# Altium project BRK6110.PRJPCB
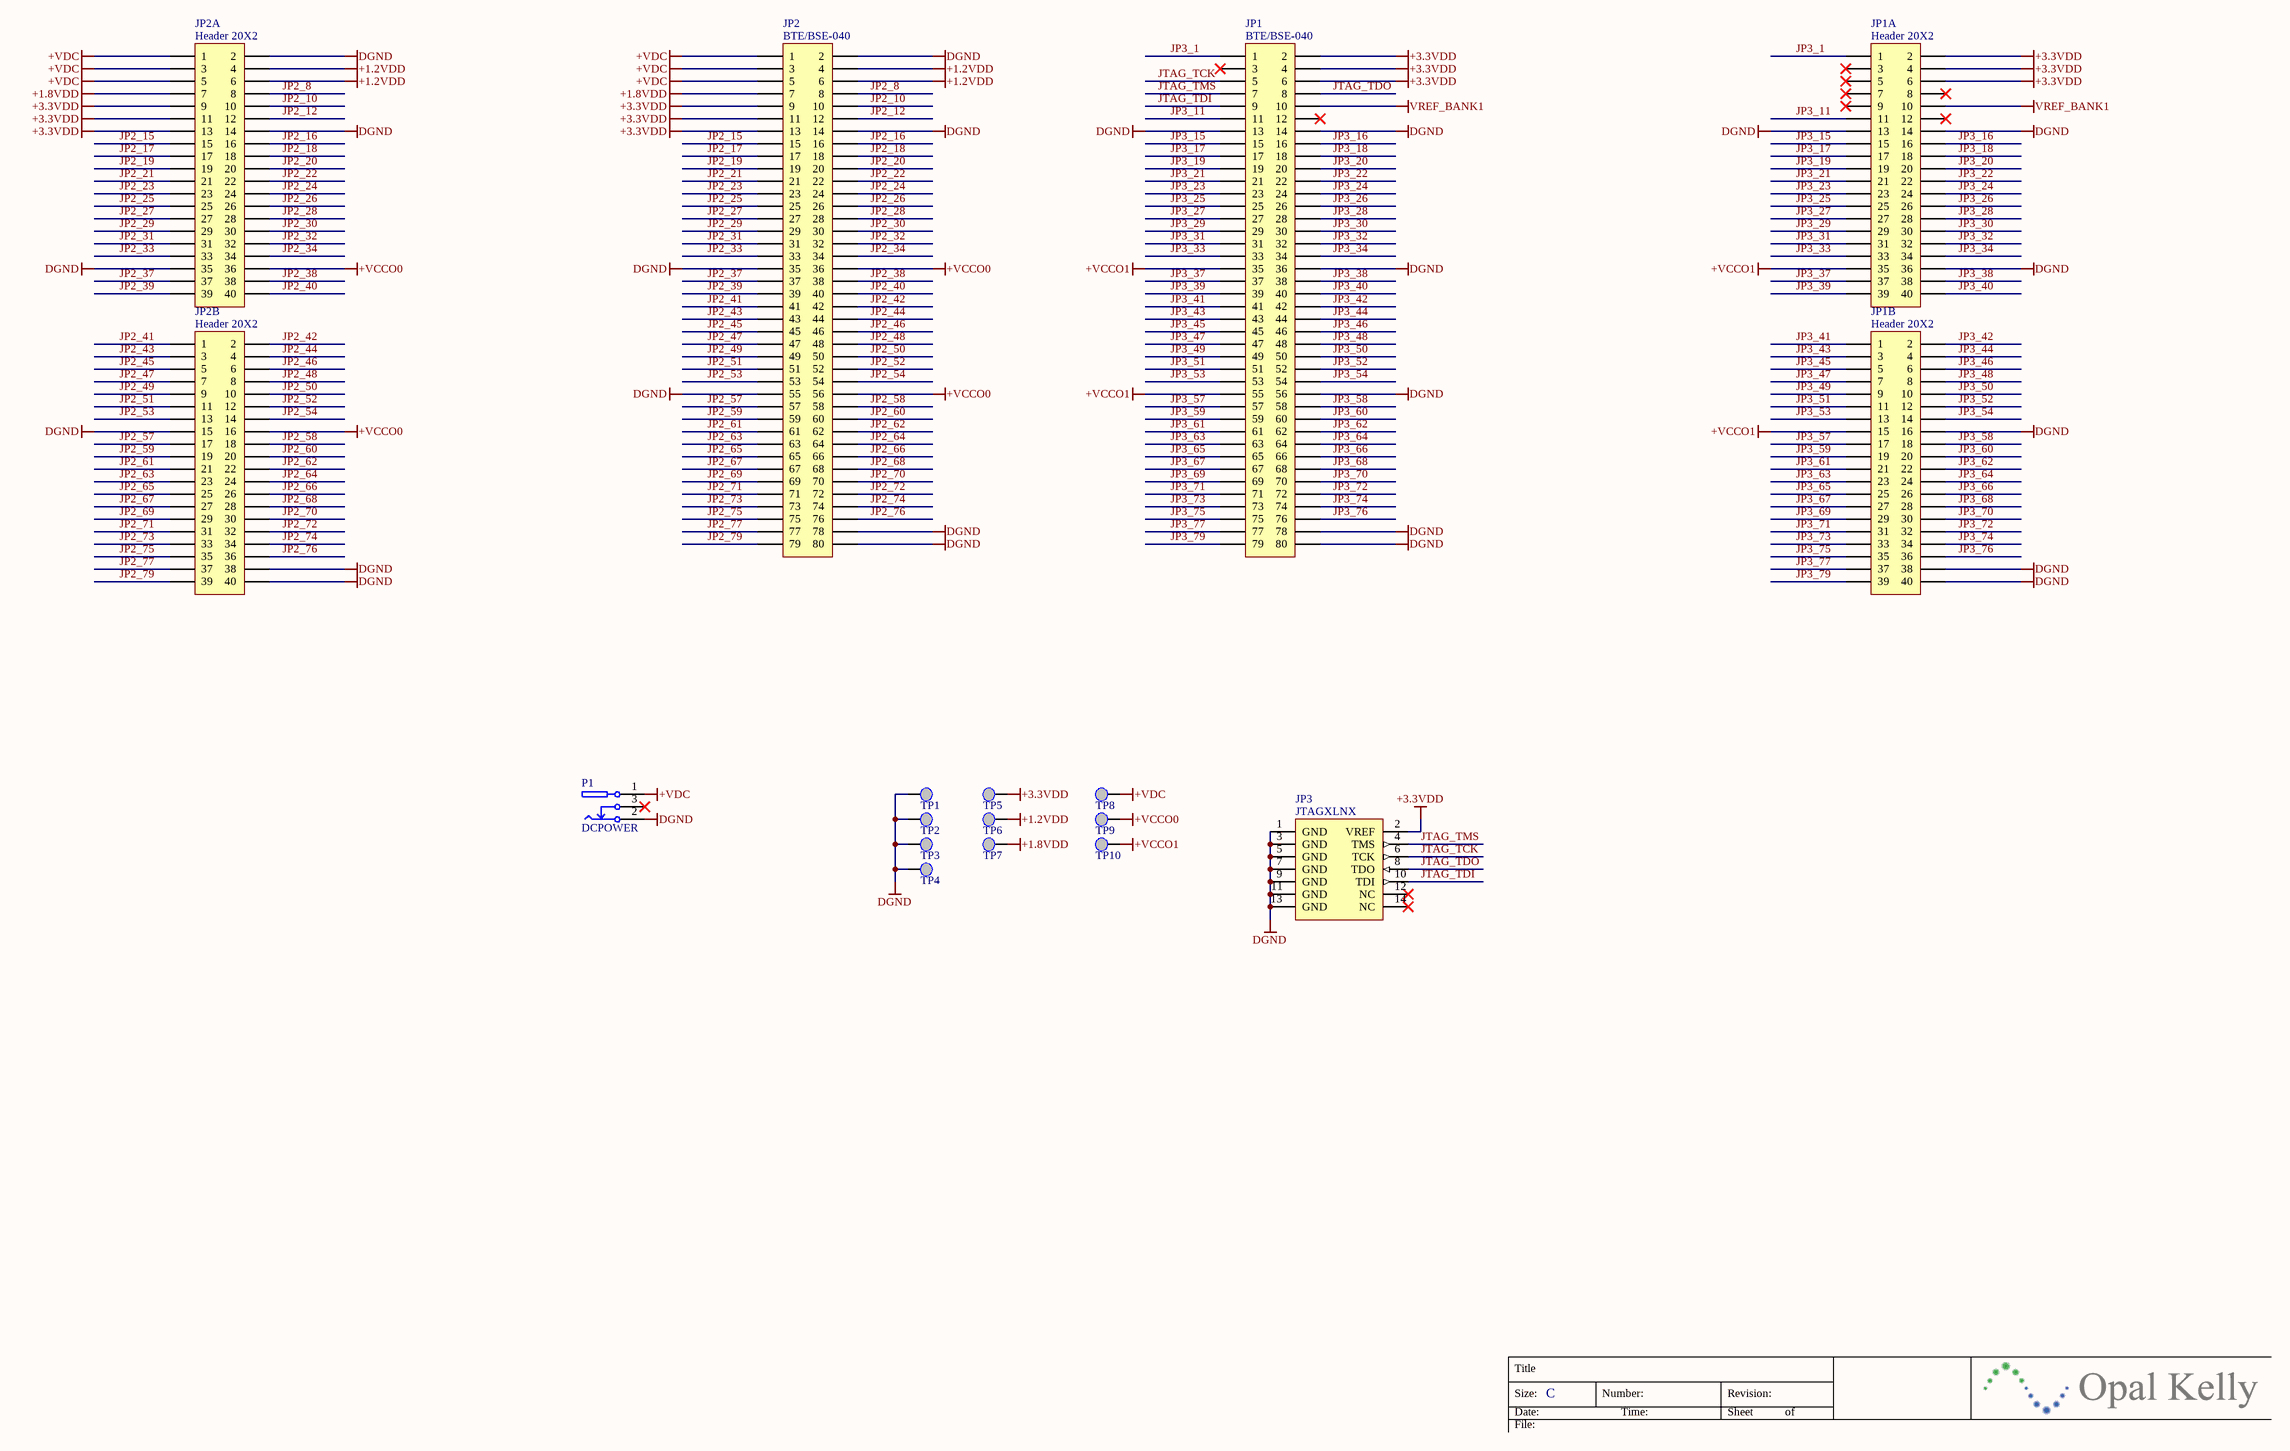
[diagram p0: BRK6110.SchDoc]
1 sheet, 18 parts. Net scope: global (net labels, ports and power ports of the same name join across sheets).
Board file: BRK6110.PcbDoc

## Sheet BRK6110.SchDoc: BRK6110
size C; Author: Jake Janovetz; Organization: Opal Kelly; Address1: 13500 SW 72nd Ave, STE 120; Address2: Portland, OR 97223; Address4: http://www.opalkelly.com; DocumentNumber: xxx; Revision: 1; SheetNumber: 1; SheetTotal: 1; PageSetup: Record=PageOptions|CenterHorizontal=True|CenterVertical=True|PrintScale=0.54|XCorrection=1.00|YCorrection=1.00|PrintKind=0|BorderSize=5000000|LeftOffset=0|BottomOffset=0|Orientation=2|PaperLength=1000|PaperWidth=1000|Scale=100|PaperSource=7|PrintQuality=-4|MediaType=1|DitherType=10|PaperKind=Letter|PrintScaleMode=1

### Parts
JP1  BTE/BSE-040  [BTE-040]
JP1A  Header 20X2  [HDR2X20-2MM]
JP1B  Header 20X2  [HDR2X20-2MM]
JP2  BTE/BSE-040  [BTE-040]
JP2A  Header 20X2  [HDR2X20-2MM]
JP2B  Header 20X2  [HDR2X20-2MM]
JP3  JTAGXLNX  [HDR2X7-2MM]
P1  DCPOWER  [CUI-PJ102A]
TP1  TESTPOINT  [TP_MED]  (value not drawn)
TP2  TESTPOINT  [TP_MED]  (value not drawn)
TP3  TESTPOINT  [TP_MED]  (value not drawn)
TP4  TESTPOINT  [TP_MED]  (value not drawn)
TP5  TESTPOINT  [TP_MED]  (value not drawn)
TP6  TESTPOINT  [TP_MED]  (value not drawn)
TP7  TESTPOINT  [TP_MED]  (value not drawn)
TP8  TESTPOINT  [TP_MED]  (value not drawn)
TP9  TESTPOINT  [TP_MED]  (value not drawn)
TP10  TESTPOINT  [TP_MED]  (value not drawn)

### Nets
+1.2VDD: JP2.4 JP2.6 JP2A.4 JP2A.6 TP6.1(PIN)
+1.8VDD: JP2.7 JP2A.7 TP7.1(PIN)
+3.3VDD: JP1.2 JP1.4 JP1.6 JP1A.2 JP1A.4 JP1A.6 JP2.9 JP2.11 JP2.13 JP2A.9 JP2A.11 JP2A.13 JP3.2(VREF) TP5.1(PIN)
+VCCO0: JP2.36 JP2.56 JP2A.36 JP2B.16 TP9.1(PIN)
+VCCO1: JP1.35 JP1.55 JP1A.35 JP1B.15 TP10.1(PIN)
+VDC: JP2.1 JP2.3 JP2.5 JP2A.1 JP2A.3 JP2A.5 P1.1 TP8.1(PIN)
DGND: JP1.13 JP1.14 JP1.36 JP1.56 JP1.78 JP1.80 JP1A.13 JP1A.14 JP1A.36 JP1B.16 JP1B.38 JP1B.40 JP2.2 JP2.14 JP2.35 JP2.55 JP2.78 JP2.80 JP2A.2 JP2A.14 JP2A.35 JP2B.15 JP2B.38 JP2B.40 JP3.1(GND) JP3.3(GND) JP3.5(GND) JP3.7(GND) JP3.9(GND) JP3.11(GND) JP3.13(GND) P1.2 TP1.1(PIN) TP2.1(PIN) TP3.1(PIN) TP4.1(PIN)
VREF_BANK1: JP1.10 JP1A.10
JP2_8: JP2.8 JP2A.8
JP2_10: JP2.10 JP2A.10
JP2_12: JP2.12 JP2A.12
JP2_15: JP2.15 JP2A.15
JP2_16: JP2.16 JP2A.16
JP2_17: JP2.17 JP2A.17
JP2_18: JP2.18 JP2A.18
JP2_19: JP2.19 JP2A.19
JP2_20: JP2.20 JP2A.20
JP2_21: JP2.21 JP2A.21
JP2_22: JP2.22 JP2A.22
JP2_23: JP2.23 JP2A.23
JP2_24: JP2.24 JP2A.24
JP2_25: JP2.25 JP2A.25
JP2_26: JP2.26 JP2A.26
JP2_27: JP2.27 JP2A.27
JP2_28: JP2.28 JP2A.28
JP2_29: JP2.29 JP2A.29
JP2_30: JP2.30 JP2A.30
JP2_31: JP2.31 JP2A.31
JP2_32: JP2.32 JP2A.32
JP2_33: JP2.33 JP2A.33
JP2_34: JP2.34 JP2A.34
JP2_37: JP2.37 JP2A.37
JP2_38: JP2.38 JP2A.38
JP2_39: JP2.39 JP2A.39
JP2_40: JP2.40 JP2A.40
JP2_41: JP2.41 JP2B.1
JP2_42: JP2.42 JP2B.2
JP2_43: JP2.43 JP2B.3
JP2_44: JP2.44 JP2B.4
JP2_45: JP2.45 JP2B.5
JP2_46: JP2.46 JP2B.6
JP2_47: JP2.47 JP2B.7
JP2_48: JP2.48 JP2B.8
JP2_49: JP2.49 JP2B.9
JP2_50: JP2.50 JP2B.10
JP2_51: JP2.51 JP2B.11
JP2_52: JP2.52 JP2B.12
JP2_53: JP2.53 JP2B.13
JP2_54: JP2.54 JP2B.14
JP2_57: JP2.57 JP2B.17
JP2_58: JP2.58 JP2B.18
JP2_59: JP2.59 JP2B.19
JP2_60: JP2.60 JP2B.20
JP2_61: JP2.61 JP2B.21
JP2_62: JP2.62 JP2B.22
JP2_63: JP2.63 JP2B.23
JP2_64: JP2.64 JP2B.24
JP2_65: JP2.65 JP2B.25
JP2_66: JP2.66 JP2B.26
JP2_67: JP2.67 JP2B.27
JP2_68: JP2.68 JP2B.28
JP2_69: JP2.69 JP2B.29
JP2_70: JP2.70 JP2B.30
JP2_71: JP2.71 JP2B.31
JP2_72: JP2.72 JP2B.32
JP2_73: JP2.73 JP2B.33
JP2_74: JP2.74 JP2B.34
JP2_75: JP2.75 JP2B.35
JP2_76: JP2.76 JP2B.36
JP2_77: JP2.77 JP2B.37
JP2_79: JP2.79 JP2B.39
JP3_1: JP1.1 JP1A.1
JP3_11: JP1.11 JP1A.11
JP3_15: JP1.15 JP1A.15
JP3_16: JP1.16 JP1A.16
JP3_17: JP1.17 JP1A.17
JP3_18: JP1.18 JP1A.18
JP3_19: JP1.19 JP1A.19
JP3_20: JP1.20 JP1A.20
JP3_21: JP1.21 JP1A.21
JP3_22: JP1.22 JP1A.22
JP3_23: JP1.23 JP1A.23
JP3_24: JP1.24 JP1A.24
JP3_25: JP1.25 JP1A.25
JP3_26: JP1.26 JP1A.26
JP3_27: JP1.27 JP1A.27
JP3_28: JP1.28 JP1A.28
JP3_29: JP1.29 JP1A.29
JP3_30: JP1.30 JP1A.30
JP3_31: JP1.31 JP1A.31
JP3_32: JP1.32 JP1A.32
JP3_33: JP1.33 JP1A.33
JP3_34: JP1.34 JP1A.34
JP3_37: JP1.37 JP1A.37
JP3_38: JP1.38 JP1A.38
JP3_39: JP1.39 JP1A.39
JP3_40: JP1.40 JP1A.40
JP3_41: JP1.41 JP1B.1
JP3_42: JP1.42 JP1B.2
JP3_43: JP1.43 JP1B.3
JP3_44: JP1.44 JP1B.4
JP3_45: JP1.45 JP1B.5
JP3_46: JP1.46 JP1B.6
JP3_47: JP1.47 JP1B.7
JP3_48: JP1.48 JP1B.8
JP3_49: JP1.49 JP1B.9
JP3_50: JP1.50 JP1B.10
JP3_51: JP1.51 JP1B.11
JP3_52: JP1.52 JP1B.12
JP3_53: JP1.53 JP1B.13
JP3_54: JP1.54 JP1B.14
JP3_57: JP1.57 JP1B.17
JP3_58: JP1.58 JP1B.18
JP3_59: JP1.59 JP1B.19
JP3_60: JP1.60 JP1B.20
JP3_61: JP1.61 JP1B.21
JP3_62: JP1.62 JP1B.22
JP3_63: JP1.63 JP1B.23
JP3_64: JP1.64 JP1B.24
JP3_65: JP1.65 JP1B.25
JP3_66: JP1.66 JP1B.26
JP3_67: JP1.67 JP1B.27
JP3_68: JP1.68 JP1B.28
JP3_69: JP1.69 JP1B.29
JP3_70: JP1.70 JP1B.30
JP3_71: JP1.71 JP1B.31
JP3_72: JP1.72 JP1B.32
JP3_73: JP1.73 JP1B.33
JP3_74: JP1.74 JP1B.34
JP3_75: JP1.75 JP1B.35
JP3_76: JP1.76 JP1B.36
JP3_77: JP1.77 JP1B.37
JP3_79: JP1.79 JP1B.39
JTAG_TCK: JP1.5 JP3.6(TCK)
JTAG_TDI: JP1.9 JP3.10(TDI)
JTAG_TDO: JP1.8 JP3.8(TDO)
JTAG_TMS: JP1.7 JP3.4(TMS)

Not connected (* = marked no-connect by the designer): JP1 3* 12*; JP1A 3* 5* 7* 8* 9* 12*; JP3 12(NC)* 14(NC)*; P1 3*

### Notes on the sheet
- Title
- Size:
- Date:
- File:
- C
- Number:
- Time:
- Revision:
- Sheet
- of

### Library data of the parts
JP1 JP2 = BTE/BSE-040: Header/Socket - 80-pin - 0.80mm; Manufacturer: Samtech; PartNumber: 000059
JP1A JP1B JP2A JP2B = Header 20X2: Header, 20-Pin, Dual row; Manufacturer: Generic Components; Class I: Connector
JP3 = JTAGXLNX: Xilinx JTAG Header, 7-Pin, Dual row; Manufacturer: Generic Components; PartNumber: 000541; Class I: Connector
P1 = DCPOWER: DC Power Connector; Manufacturer: CUI, Inc.; PartNumber: 000356
TP1-TP10 = TESTPOINT: PartNumber: 000042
